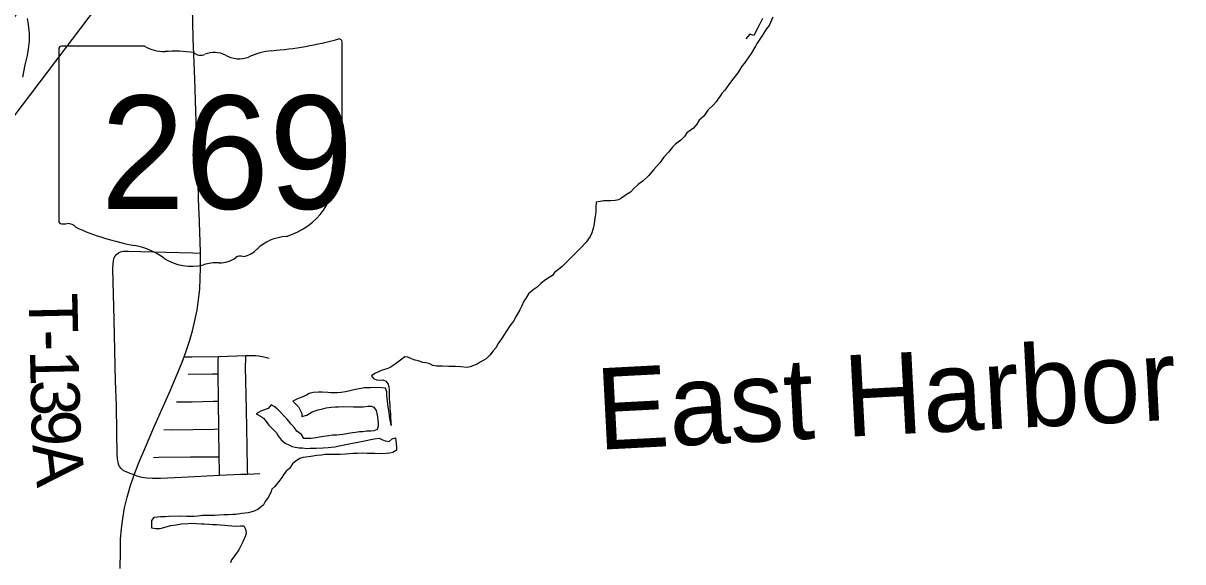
# Model space of a CAD drawing. Extents: x -12 to 34, y 0 to 22.
# Drawn here: x 2.907 to 4.257, y 18.019 to 18.646 of the extents above; entities that cross this region are included whole.
import ezdxf

# ---------------------------------------------------------------- set-up
doc = ezdxf.new("R2010")
doc.units = 0
for name, color, linetype in [('GM_X_Adjacent_County', 7, 'Continuous'), ('GM_X_County_Road_Text', 7, 'Continuous'), ('GM_X_Major_Lake', 7, 'Continuous'), ('GM_X_Major_River', 7, 'Continuous'), ('GM_X_Minor_Lake', 7, 'Continuous'), ('GM_X_Minor_River_Text', 7, 'Continuous'), ('GM_X_Township_Road_Text', 7, 'Continuous'), ('GM_X_Township_Text', 7, 'Continuous')]:
    doc.layers.add(name, color=color, linetype=linetype)

msp = doc.modelspace()

# ---------------------------------------------------------------- linework, layer by layer
at = {"layer": 'GM_X_Adjacent_County'}
msp.add_lwpolyline([(4.3077, 20.7695), (2.2584, 17.6954), (4.3077, 20.4)], close=True, dxfattribs=at)
at = {"layer": 'GM_X_Major_Lake'}
for points in [[(3.112, 18.4296), (3.111, 18.4583), (3.1088, 18.5316), (3.1072, 18.5808), (3.1055, 18.6279), (3.105, 18.6478), (3.1045, 18.6622), (3.1033, 18.705), (3.1005, 18.7978), (3.0996, 18.8346), (3.0993, 18.8434)], [(3.0205, 18.011), (3.0207, 18.0308), (3.0209, 18.0453), (3.0219, 18.0575), (3.0235, 18.0693), (3.0255, 18.0815), (3.0283, 18.0939), (3.0325, 18.1075), (3.036, 18.1177), (3.0368, 18.1201), (3.0426, 18.1352), (3.0497, 18.1524), (3.0596, 18.1752), (3.0785, 18.2179), (3.0918, 18.2494), (3.0948, 18.2574), (3.0973, 18.2639), (3.1012, 18.2757), (3.1045, 18.2876), (3.1074, 18.2997), (3.1098, 18.3118), (3.1116, 18.3241), (3.1129, 18.3364), (3.1136, 18.3488), (3.1138, 18.3612), (3.1137, 18.3783), (3.1137, 18.3798), (3.1122, 18.4256), (3.112, 18.4296)]]:
    msp.add_lwpolyline(points, dxfattribs=at)
at = {"layer": 'GM_X_Major_River'}
for p, q in [((3.1347, 18.2579), (3.1667, 18.2589)), ((3.1353, 18.1735), (3.1349, 18.2058)), ((3.1357, 18.1411), (3.1353, 18.1735)), ((3.1688, 18.121), (3.1828, 18.1215))]:
    msp.add_line(p, q, dxfattribs=at)
for points in [[(3.0193, 18.1307), (3.0185, 18.1324), (3.0178, 18.1353), (3.0174, 18.1383), (3.0169, 18.144), (3.0163, 18.1692), (3.0159, 18.2007), (3.0147, 18.2297), (3.0135, 18.3005), (3.0119, 18.3598), (3.012, 18.366), (3.0124, 18.369), (3.0131, 18.3718), (3.0143, 18.3744), (3.016, 18.3766), (3.0183, 18.3784), (3.0209, 18.3796), (3.0239, 18.3803), (3.0268, 18.3806), (3.0299, 18.3806), (3.0736, 18.3793), (3.1048, 18.3785), (3.1137, 18.3783)], [(3.0948, 18.2574), (3.1037, 18.2575), (3.1347, 18.2579)], [(3.1345, 18.2375), (3.1344, 18.2445), (3.1346, 18.2539), (3.1347, 18.2579)], [(3.1688, 18.121), (3.1687, 18.1247), (3.1687, 18.1278), (3.168, 18.1526), (3.1674, 18.1961), (3.1664, 18.2458), (3.1666, 18.2551), (3.1667, 18.2589)], [(3.1667, 18.2589), (3.1691, 18.259), (3.1784, 18.2589), (3.1815, 18.2586), (3.1877, 18.2575), (3.1937, 18.256)], [(3.0995, 18.2374), (3.1277, 18.2375), (3.1345, 18.2375)], [(3.1349, 18.2058), (3.1349, 18.2067), (3.1345, 18.2375)], [(3.086, 18.205), (3.0921, 18.2049), (3.1042, 18.2052), (3.1285, 18.2057), (3.1349, 18.2058)], [(3.0712, 18.1729), (3.0805, 18.1726), (3.1298, 18.1734), (3.1353, 18.1735)], [(3.0368, 18.1201), (3.0333, 18.1214), (3.0261, 18.124), (3.0235, 18.1256), (3.0213, 18.1275), (3.0197, 18.1298), (3.0193, 18.1307)], [(3.0593, 18.1404), (3.0654, 18.1406), (3.1023, 18.1411), (3.13, 18.1411), (3.1357, 18.1411)], [(3.136, 18.1196), (3.1359, 18.1249), (3.1357, 18.1411)], [(3.0368, 18.1201), (3.0408, 18.1185), (3.0456, 18.1173), (3.0517, 18.1164), (3.058, 18.1161), (3.0673, 18.1162), (3.0923, 18.1174), (3.136, 18.1196)], [(3.136, 18.1196), (3.1609, 18.1208), (3.1688, 18.121)]]:
    msp.add_lwpolyline(points, dxfattribs=at)
at = {"layer": 'GM_X_Minor_Lake'}
for points in [[(2.9072, 18.583), (2.9098, 18.5974), (2.9124, 18.6081), (2.9135, 18.6161), (2.9146, 18.6245), (2.9146, 18.634), (2.9137, 18.6442), (2.9126, 18.6514)], [(3.7801, 18.6529), (3.776, 18.6433), (3.7722, 18.6388), (3.768, 18.6319), (3.762, 18.6227), (3.7601, 18.6193), (3.7549, 18.6105), (3.7466, 18.5991), (3.7439, 18.5957), (3.7394, 18.588), (3.7334, 18.5808), (3.7307, 18.5774), (3.7243, 18.5678), (3.7209, 18.564), (3.7141, 18.5545), (3.7111, 18.551), (3.7043, 18.5445), (3.6998, 18.5377), (3.6945, 18.5331), (3.6915, 18.5285), (3.6877, 18.5235), (3.6802, 18.5182), (3.6775, 18.514), (3.673, 18.5098), (3.6669, 18.5052), (3.6632, 18.5014), (3.6586, 18.4957), (3.6534, 18.4899), (3.6484, 18.4834), (3.6413, 18.475), (3.6356, 18.4686), (3.6292, 18.4624), (3.6235, 18.4579), (3.6182, 18.4533), (3.6145, 18.4491), (3.6099, 18.4464), (3.6039, 18.4422), (3.6005, 18.4403), (3.5967, 18.4395), (3.5917, 18.4391), (3.583, 18.439), (3.5792, 18.4383), (3.5746, 18.4375), (3.5739, 18.431), (3.5739, 18.4272), (3.5736, 18.423), (3.5728, 18.4192), (3.5721, 18.4124), (3.571, 18.407), (3.5695, 18.4017), (3.5673, 18.3975), (3.5627, 18.391), (3.5571, 18.3849), (3.5408, 18.3685), (3.5348, 18.3628), (3.5306, 18.3593), (3.5261, 18.3555), (3.5235, 18.3521), (3.5178, 18.3486), (3.514, 18.346), (3.5102, 18.3429), (3.5057, 18.3387), (3.5011, 18.3356), (3.4958, 18.3307), (3.4928, 18.3261), (3.4902, 18.3223), (3.4876, 18.3162), (3.4857, 18.312), (3.4815, 18.3047), (3.4782, 18.299), (3.474, 18.2937), (3.4706, 18.288), (3.4669, 18.2826), (3.4642, 18.2784), (3.4605, 18.2731), (3.4578, 18.2681), (3.4544, 18.2643), (3.4507, 18.2594)], [(3.7801, 18.6529), (3.776, 18.6433), (3.7722, 18.6388), (3.768, 18.6319), (3.762, 18.6227), (3.7601, 18.6193), (3.7549, 18.6105), (3.7466, 18.5991), (3.7439, 18.5957), (3.7394, 18.588), (3.7334, 18.5808), (3.7307, 18.5774), (3.7243, 18.5678), (3.7209, 18.564), (3.7141, 18.5545), (3.7111, 18.551), (3.7043, 18.5445), (3.6998, 18.5377), (3.6945, 18.5331), (3.6915, 18.5285), (3.6877, 18.5235), (3.6802, 18.5182), (3.6775, 18.514), (3.673, 18.5098), (3.6669, 18.5052), (3.6632, 18.5014), (3.6586, 18.4957), (3.6534, 18.4899), (3.6484, 18.4834), (3.6413, 18.475), (3.6356, 18.4686), (3.6292, 18.4624), (3.6235, 18.4579), (3.6182, 18.4533), (3.6145, 18.4491), (3.6099, 18.4464), (3.6039, 18.4422), (3.6005, 18.4403), (3.5967, 18.4395), (3.5917, 18.4391), (3.583, 18.439), (3.5792, 18.4383), (3.5746, 18.4375), (3.5739, 18.431), (3.5739, 18.4272), (3.5736, 18.423), (3.5728, 18.4192), (3.5721, 18.4124), (3.571, 18.407), (3.5695, 18.4017), (3.5673, 18.3975), (3.5627, 18.391), (3.5571, 18.3849), (3.5408, 18.3685), (3.5348, 18.3628), (3.5306, 18.3593), (3.5261, 18.3555), (3.5235, 18.3521), (3.5178, 18.3486), (3.514, 18.346), (3.5102, 18.3429), (3.5057, 18.3387), (3.5011, 18.3356), (3.4958, 18.3307), (3.4928, 18.3261), (3.4902, 18.3223), (3.4876, 18.3162), (3.4857, 18.312), (3.4815, 18.3047), (3.4782, 18.299), (3.474, 18.2937), (3.4706, 18.288), (3.4669, 18.2826), (3.4642, 18.2784), (3.4605, 18.2731), (3.4578, 18.2681), (3.4544, 18.2643), (3.4507, 18.2594)], [(3.7683, 18.6513), (3.7646, 18.6444), (3.7582, 18.6315), (3.7532, 18.633), (3.7487, 18.6276)], [(3.4507, 18.2594), (3.4465, 18.2552), (3.4393, 18.2513), (3.4359, 18.249), (3.4276, 18.2459), (3.4241, 18.2452), (3.4169, 18.2459), (3.4109, 18.2463), (3.4029, 18.2462), (3.3953, 18.2466), (3.3885, 18.2465), (3.3843, 18.2473), (3.3808, 18.2492), (3.3763, 18.2506), (3.3725, 18.251), (3.3672, 18.2529), (3.3637, 18.2536), (3.3596, 18.2551), (3.3554, 18.257), (3.3516, 18.2574), (3.3451, 18.2524), (3.3383, 18.2474), (3.3345, 18.2451), (3.3308, 18.2436), (3.3255, 18.242), (3.3217, 18.2405), (3.3167, 18.2382), (3.313, 18.2355), (3.3153, 18.2321), (3.3187, 18.2306), (3.3229, 18.2302), (3.3263, 18.2306), (3.3297, 18.2291), (3.3324, 18.2257), (3.3331, 18.2223), (3.3335, 18.2189), (3.3336, 18.2086), (3.334, 18.2045), (3.3344, 18.201), (3.3344, 18.1972), (3.3352, 18.1912), (3.3352, 18.1873), (3.3356, 18.1813), (3.3357, 18.1775), (3.3352, 18.182), (3.3341, 18.1858), (3.3333, 18.1927), (3.3325, 18.1987), (3.3309, 18.2128), (3.3309, 18.2166), (3.3294, 18.2208), (3.3214, 18.2219), (3.3115, 18.2215), (3.3043, 18.2214), (3.3009, 18.2206), (3.2944, 18.2195), (3.2827, 18.2168), (3.2777, 18.216), (3.2728, 18.2156), (3.2656, 18.2155), (3.2622, 18.2159), (3.2553, 18.2162), (3.2512, 18.2162), (3.2451, 18.2158), (3.2405, 18.2147), (3.2371, 18.2127), (3.2311, 18.21), (3.2269, 18.2085), (3.2212, 18.2058), (3.2247, 18.2024), (3.2281, 18.1994), (3.2319, 18.1914), (3.232, 18.188), (3.2376, 18.1896), (3.2437, 18.1934), (3.2509, 18.1957), (3.2547, 18.1965), (3.26, 18.198), (3.2661, 18.1988), (3.271, 18.1992), (3.2744, 18.1992), (3.2805, 18.1996), (3.2919, 18.1993), (3.3033, 18.1994), (3.309, 18.2002), (3.3124, 18.2002), (3.3158, 18.199), (3.3185, 18.1949), (3.3193, 18.1915), (3.32, 18.1877), (3.3201, 18.1839), (3.3205, 18.1801), (3.3205, 18.1766), (3.3194, 18.1728), (3.3156, 18.1713), (3.3121, 18.1709), (3.3072, 18.1709), (3.303, 18.1701), (3.2989, 18.1701), (3.2943, 18.1693), (3.2909, 18.1689)], [(3.2909, 18.1689), (3.2795, 18.1669), (3.2761, 18.1665), (3.2727, 18.1661), (3.2674, 18.1661), (3.2632, 18.1653), (3.2571, 18.1646), (3.2457, 18.1626), (3.2423, 18.1622), (3.234, 18.1622), (3.2313, 18.1671), (3.226, 18.1709), (3.2233, 18.1747), (3.2195, 18.1792), (3.2149, 18.1849), (3.2107, 18.1887), (3.2073, 18.1925), (3.2031, 18.197), (3.1996, 18.1996), (3.1962, 18.2015), (3.1928, 18.1973), (3.1848, 18.1946), (3.1788, 18.1912), (3.1837, 18.1882), (3.1872, 18.1859), (3.1902, 18.1821), (3.1933, 18.1779), (3.2024, 18.1689), (3.2044, 18.1654), (3.2078, 18.1609), (3.2124, 18.1571), (3.2173, 18.1545), (3.2207, 18.153), (3.2242, 18.1522), (3.2287, 18.1515), (3.2321, 18.1515), (3.2382, 18.1508), (3.2416, 18.1512), (3.2485, 18.1512), (3.2568, 18.1516), (3.2625, 18.152), (3.2659, 18.1524), (3.2701, 18.1528), (3.2735, 18.1536), (3.2849, 18.1556), (3.3027, 18.1591), (3.316, 18.1618), (3.3217, 18.1626), (3.3251, 18.1611), (3.3289, 18.1596), (3.3335, 18.1588), (3.3369, 18.1619), (3.3407, 18.163), (3.3418, 18.1566), (3.3422, 18.1524), (3.3419, 18.1486), (3.3377, 18.1459), (3.3343, 18.1452), (3.3301, 18.1448), (3.3218, 18.1447), (3.3168, 18.1451), (3.3077, 18.145), (3.302, 18.1454), (3.2967, 18.145), (3.2914, 18.1449), (3.2827, 18.1441), (3.2766, 18.1437), (3.2584, 18.1437), (3.2546, 18.1429), (3.2493, 18.1425), (3.2424, 18.1413), (3.2364, 18.1405), (3.233, 18.1401), (3.2295, 18.139), (3.2254, 18.1363), (3.2208, 18.1328), (3.2175, 18.1275), (3.2137, 18.1244), (3.2103, 18.1202), (3.2084, 18.1168), (3.205, 18.1122), (3.2005, 18.1065), (3.1967, 18.1034), (3.1956, 18.0996), (3.1926, 18.0935), (3.1892, 18.089), (3.1873, 18.0852), (3.1805, 18.0798), (3.1752, 18.0775), (3.1695, 18.0759), (3.1619, 18.0752), (3.1547, 18.074), (3.1513, 18.074), (3.1464, 18.0736), (3.141, 18.0735), (3.1353, 18.0731), (3.13, 18.0727), (3.1194, 18.0727), (3.116, 18.0727), (3.1107, 18.0719), (3.1065, 18.0715)], [(3.1065, 18.0715), (3.0978, 18.0714), (3.0906, 18.0718), (3.0765, 18.0717), (3.0727, 18.0713), (3.0674, 18.0713), (3.0636, 18.0709), (3.0594, 18.0705), (3.0568, 18.0671), (3.0568, 18.0629), (3.0568, 18.0583), (3.0618, 18.0576), (3.0667, 18.0576), (3.0792, 18.0611), (3.0857, 18.0619), (3.0917, 18.063), (3.0993, 18.0635), (3.1035, 18.0639), (3.1149, 18.0631), (3.1183, 18.0632), (3.1236, 18.0628), (3.1278, 18.0624), (3.1324, 18.0621), (3.1369, 18.0617), (3.1422, 18.0614), (3.1457, 18.061), (3.1502, 18.0606), (3.1552, 18.0603), (3.1605, 18.0607), (3.1643, 18.0607), (3.1662, 18.0569), (3.167, 18.0527), (3.1662, 18.0489), (3.1632, 18.0421), (3.1613, 18.0383), (3.1583, 18.0326), (3.1557, 18.0287), (3.1527, 18.0245), (3.15, 18.0211), (3.1489, 18.0177)]]:
    msp.add_lwpolyline(points, dxfattribs=at)
at = {"layer": 'GM_X_Township_Text'}
for p, q in [((3.0488, 18.6192), (2.9523, 18.6192)), ((3.2786, 18.5195), (3.2786, 18.6242)), ((2.949, 18.6157), (2.949, 18.4156)), ((3.2786, 18.5195), (3.2786, 18.5195))]:
    msp.add_line(p, q, dxfattribs=at)
for centre, major_axis, start_param, end_param in [((2.9528, 18.6162), (0.00382, 0), 1.712693, 3.28349), ((3.0718, 18.6424), (0.037, 0), 4.042523, 4.731795), ((3.1612, 18.892), (0.3495, 0), 4.814394, 5.042369), ((3.275, 18.6246), (0.00367, 0), 6.141152, 7.989035), ((3.0841, 18.5068), (0.133, 0), 1.404758, 1.657858), ((3.1142, 18.6172), (0.0107, 0), 3.836095, 5.185415), ((3.1299, 18.5941), (0.0222, 0), 0.950623, 2.079405), ((3.1586, 18.6258), (0.0267, 0), 4.081561, 5.145723), ((3.2058, 18.5581), (0.0703, 0), 1.699011, 2.107814), ((3.2778, 18.5118), (0.00568, 0), 1.883978, 3.671073), ((3.2416, 18.4985), (0.0341, 0), 5.934695, 6.695948), ((3.2747, 18.5191), (0.00393, 0), 5.05454, 6.418171), ((3.2918, 18.4757), (0.0248, 0), 2.387724, 3.262537), ((3.1808, 18.4623), (0.0874, 0), 5.101752, 6.440018), ((2.9528, 18.4152), (0.00385, 0), 3.00124, 4.508301), ((2.9534, 18.4357), (0.0294, 0), 4.665946, 4.897461), ((2.9594, 18.4041), (0.0106, 0), 0.519207, 1.627899), ((3.0933, 18.5839), (0.2524, 0), 4.195997, 4.488961), ((3.2177, 18.3594), (0.0479, 0), 1.647645, 2.488434), ((3.018, 18.3257), (0.079, 0), 0.823519, 1.323587), ((3.1602, 18.3687), (0.00752, 0), 1.147584, 2.315152), ((3.157, 18.3962), (0.0282, 0), 4.937069, 5.64225), ((3.1034, 18.4031), (0.0501, 0), 4.026481, 4.996735), ((3.1324, 18.3339), (0.0412, 0), 1.495662, 1.94098), ((3.136, 18.3881), (0.0267, 0), 4.691044, 5.507374)]:
    msp.add_ellipse(centre, major_axis=major_axis, ratio=0.8, start_param=start_param, end_param=end_param, dxfattribs=at)

# ---------------------------------------------------------------- texts
at = {"layer": 'GM_X_County_Road_Text'}
for s, rotation, p in [('T', 271.2601, (2.9137, 18.3311)), ('-', 271.2592, (2.9147, 18.2887)), ('1', 271.2649, (2.9152, 18.2653)), ('3', 271.3059, (2.916, 18.2303)), ('9', 271.4489, (2.9168, 18.1951)), ('A', 276.5164, (2.918, 18.1547))]:
    msp.add_text(s, height=0.0568, rotation=rotation, dxfattribs=at).set_placement(p)
at = {"layer": 'GM_X_Minor_River_Text'}
msp.add_text('East Harbor', height=0.094756, rotation=3.0066, dxfattribs=at).set_placement((3.5769, 18.1491))
at = {"layer": 'GM_X_Township_Road_Text'}
for s in ['s', 'r']:
    msp.add_text(s, height=0.000189, dxfattribs=at).set_placement((3.1101, 18.5024))
msp.add_text('269', height=0.000189, rotation=0, dxfattribs=at).set_placement((3.0433, 18.4886))
at = {"layer": 'GM_X_Township_Text'}
msp.add_text('269', height=0.13184, dxfattribs=at).set_placement((2.9975, 18.4297))

doc.saveas('drawing.dxf')
